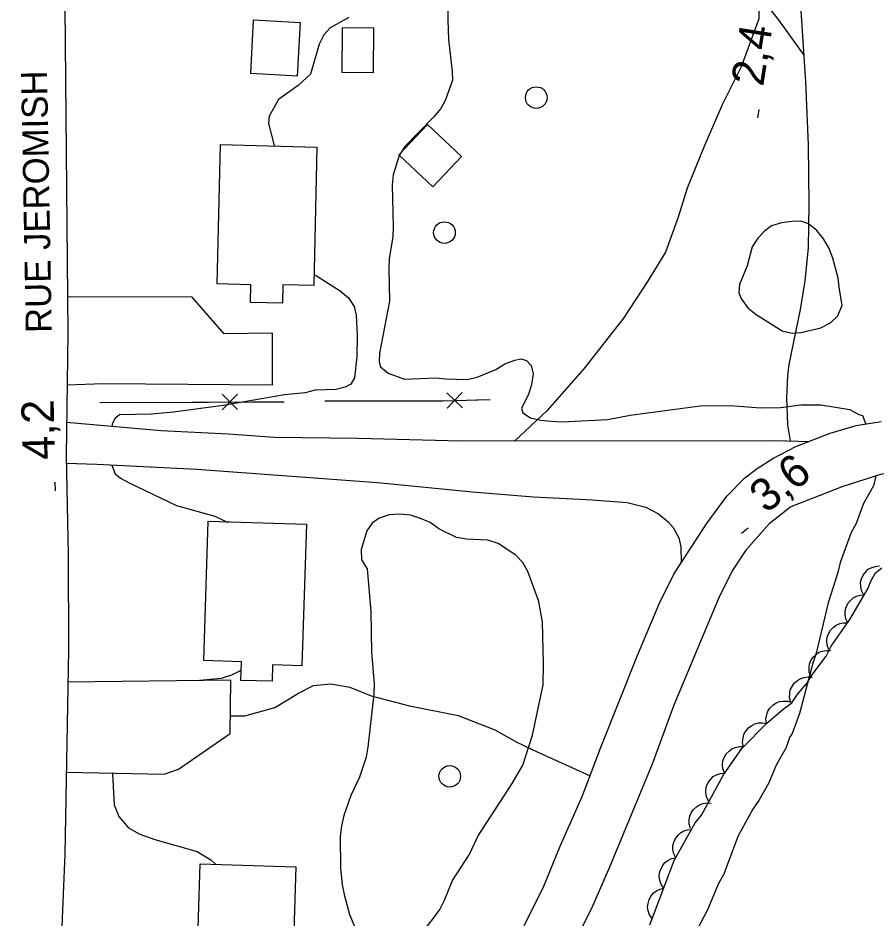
# Model space of a CAD drawing. Extents: x 282461 to 284471, y 5554090 to 5557646.
# Drawn here: x 283146.3 to 283225.6, y 5554850.5 to 5554933.8 of the extents above; entities that cross this region are included whole.
import ezdxf

# ---------------------------------------------------------------- set-up
doc = ezdxf.new("R2010")
doc.units = 0
for name, color, linetype in [('Niveau 15', 7, 'Continuous'), ('Niveau 19', 7, 'Continuous'), ('Niveau 2', 7, 'Continuous'), ('Niveau 21', 7, 'Continuous'), ('Niveau 22', 7, 'Continuous'), ('Niveau 3', 7, 'Continuous'), ('Niveau 31', 7, 'Continuous'), ('Niveau 36', 7, 'Continuous'), ('Niveau 37', 7, 'Continuous'), ('Niveau 44', 7, 'Continuous')]:
    doc.layers.add(name, color=color, linetype=linetype)

msp = doc.modelspace()

# ---------------------------------------------------------------- linework, layer by layer
at = {"layer": 'Niveau 19'}
for points in [[(283150.81, 5554899.91), (283154.12, 5554900.01), (283169.76, 5554899.91), (283169.76, 5554904.66), (283165.3, 5554904.62), (283162.36, 5554908.01), (283150.83, 5554908.02)], [(283150.76, 5554896.45), (283159.48, 5554895.68), (283165.68, 5554895.37), (283169.97, 5554895.05), (283177.68, 5554894.98), (283187.19, 5554894.71), (283216.24, 5554894.76), (283219.32, 5554894.67)], [(283150.73, 5554892.66), (283153.56, 5554892.58), (283162.77, 5554892.1), (283179.46, 5554890.87), (283188.23, 5554890.02), (283193.86, 5554889.56), (283199.32, 5554889.28), (283202.51, 5554889.03), (283204.26, 5554888.59), (283205.42, 5554887.98), (283206.3, 5554887.23), (283206.77, 5554886.71), (283207.31, 5554885.75), (283207.49, 5554884.94), (283207.51, 5554883.48)], [(283150.71, 5554864.1), (283159.76, 5554863.92), (283161.09, 5554864.39), (283165.86, 5554867.68), (283165.91, 5554872.6), (283150.88, 5554872.43)]]:
    msp.add_lwpolyline(points, dxfattribs=at)
at = {"layer": 'Niveau 2'}
for points in [[(283186, 5554935.57), (283185.96, 5554933.6), (283186.04, 5554931.8), (283186.37, 5554928.85), (283186.38, 5554928.04), (283185.76, 5554926.23), (283185.31, 5554925.42), (283184.68, 5554924.66), (283181.99, 5554921.91)], [(283176.82, 5554933.83), (283175.09, 5554932.89), (283174.52, 5554932.25), (283174.07, 5554931.38), (283173.29, 5554928.59), (283172.15, 5554927.54), (283170.31, 5554926.25), (283169.46, 5554924.73), (283169.41, 5554924.04), (283169.94, 5554922.01)], [(283181.99, 5554921.91), (283181.47, 5554921.1), (283180.92, 5554919.29), (283180.81, 5554918.37), (283180.92, 5554914.48), (283180.87, 5554913.56), (283180.55, 5554911.58), (283180.5, 5554910.6), (283180.59, 5554907.64), (283179.66, 5554902.82), (283179.62, 5554902.01), (283179.74, 5554901.55), (283180.44, 5554900.98), (283181.96, 5554900.41), (283184.85, 5554900.55), (283185.78, 5554900.44), (283187.76, 5554900.4), (283188.68, 5554900.59), (283190.41, 5554901.3), (283191.22, 5554901.83), (283192.14, 5554902.18), (283192.72, 5554902.3), (283193.24, 5554902.13), (283193.66, 5554901.67), (283193.84, 5554900.92), (283193.68, 5554899.94), (283193.4, 5554899.01), (283192.78, 5554897.73), (283192.9, 5554897.32), (283193.6, 5554896.86), (283194.53, 5554896.64), (283195.52, 5554896.53), (283196.5, 5554896.48), (283200.73, 5554896.7), (283202.79, 5554897.09), (283209.28, 5554897.96), (283212.06, 5554897.98), (283214.85, 5554897.78), (283216.7, 5554897.79), (283218.56, 5554898.04), (283220.41, 5554898.06), (283223.09, 5554897.62), (283223.91, 5554897.16), (283224.25, 5554897.05), (283224.56, 5554896.27)], [(283222.12, 5554908.72), (283222, 5554909.76), (283221.51, 5554911.61), (283221.15, 5554912.54), (283220.67, 5554913.4), (283220.03, 5554914.15), (283219.26, 5554914.78), (283218.56, 5554915.01), (283217.75, 5554915), (283216.77, 5554914.88), (283215.84, 5554914.58), (283215.21, 5554914.11), (283214.58, 5554913.46), (283214.06, 5554912.65), (283213.62, 5554910.9), (283212.89, 5554909.16), (283212.84, 5554908.4), (283213.08, 5554907.82), (283213.67, 5554907.02), (283214.43, 5554906.39), (283216.83, 5554904.9), (283217.76, 5554904.68), (283218.57, 5554904.74), (283220.42, 5554905.16), (283221.29, 5554905.64), (283221.98, 5554906.28), (283222.37, 5554907.27), (283222.12, 5554908.72)], [(283173.75, 5554910.04), (283176.03, 5554908.58), (283176.79, 5554907.95), (283177.32, 5554907.14), (283177.5, 5554906.33), (283177.58, 5554904.42), (283177.55, 5554902.51), (283177.34, 5554900.54), (283177, 5554899.96), (283176.48, 5554899.67), (283175.61, 5554899.48), (283173.7, 5554899.41), (283172.78, 5554899.17), (283170.87, 5554898.98), (283165.2, 5554898), (283160.63, 5554897.38)], [(283160.63, 5554897.38), (283158.61, 5554897.19), (283155.65, 5554897.11), (283155.25, 5554896.81), (283154.97, 5554896.29), (283154.95, 5554896.12)], [(283154.94, 5554892.48), (283155.25, 5554891.66), (283155.72, 5554891.26), (283156.6, 5554890.8), (283160.91, 5554888.76), (283164.46, 5554887.75), (283165.69, 5554887.18)], [(283225.48, 5554891.5), (283225.26, 5554890.57), (283224.35, 5554888.94), (283223.68, 5554887.08), (283223.22, 5554886.26), (283222.21, 5554883.47), (283221.99, 5554882.54), (283221.1, 5554879.75), (283219.99, 5554875.1), (283219.66, 5554874.17), (283218.43, 5554869.53), (283217.76, 5554867.67), (283217.53, 5554867.32), (283217.2, 5554866.39), (283216.29, 5554864.75), (283215.61, 5554863.13), (283214.7, 5554861.5), (283214.13, 5554860.68), (283212.77, 5554858.23), (283211.42, 5554854.63), (283210.97, 5554853.81), (283209.95, 5554851.37), (283207.8, 5554847.3)], [(283183.44, 5554849.08), (283184.64, 5554850.6), (283185.21, 5554851.42), (283185.67, 5554852.29), (283186.4, 5554854.09), (283187.94, 5554856.48), (283188.78, 5554858.23), (283191.92, 5554863.06), (283192.88, 5554864.75), (283193.78, 5554867.54), (283194.76, 5554872.19), (283194.8, 5554874.16), (283194.7, 5554877.98), (283194.38, 5554879.89), (283193.36, 5554882.66), (283192.89, 5554883.47), (283192.24, 5554884.16), (283190.61, 5554885.25), (283189.67, 5554885.53), (283187.7, 5554885.63), (283186.77, 5554885.79), (283185.14, 5554886.59), (283184.32, 5554887.16), (283183.44, 5554887.56), (283182.51, 5554887.84), (283181.53, 5554887.95), (283180.54, 5554887.88), (283179.62, 5554887.58), (283178.98, 5554887.11), (283178.47, 5554886.41), (283177.97, 5554884.67), (283177.98, 5554883.74), (283178.51, 5554882.88)], [(283178.51, 5554882.88), (283178.85, 5554878.94), (283178.9, 5554875.18), (283179.16, 5554872.28), (283179.12, 5554871.3), (283178.59, 5554866.42), (283178.43, 5554865.5), (283177.82, 5554863.64), (283177.02, 5554861.95), (283176.35, 5554860.09), (283176.13, 5554859.16), (283176.03, 5554858.17), (283176.06, 5554855.28), (283176.2, 5554853.71), (283176.38, 5554852.79), (283176.87, 5554850.94), (283177.64, 5554849.15)], [(283166.85, 5554873.5), (283165.97, 5554873.06), (283165.04, 5554872.76), (283163.04, 5554872.57)], [(283155.01, 5554864.01), (283155.01, 5554863.93), (283155.16, 5554861.09), (283155.58, 5554860), (283156.46, 5554858.96), (283157.51, 5554858.39), (283158.91, 5554857.88), (283162.8, 5554856.76), (283164.08, 5554856.02), (283164.52, 5554855.6)]]:
    msp.add_lwpolyline(points, dxfattribs=at)
at = {"layer": 'Niveau 21'}
for points in [[(283150.5, 5554944.9), (283150.87, 5554904.67), (283150.72, 5554893.32), (283150.89, 5554884.23), (283150.94, 5554875.39), (283150.59, 5554856.52), (283150.09, 5554844.69), (283149.99, 5554838.96), (283149.57, 5554834.94), (283148.73, 5554831.87), (283147.21, 5554828.07), (283145.57, 5554824.59)], [(283193.02, 5554849.93), (283194.77, 5554853.42), (283196.35, 5554857.26), (283198.38, 5554861.85), (283200.06, 5554866.32), (283203.44, 5554874.81), (283205.47, 5554879.67), (283206.82, 5554882.41), (283209.84, 5554887.05), (283211.72, 5554889.61), (283213.39, 5554891.29), (283214.54, 5554892.16), (283215.97, 5554893.08), (283218.11, 5554894.19), (283221.28, 5554895.44), (283223.66, 5554896.14), (283225.97, 5554896.5)], [(283289.42, 5554896.28), (283275.18, 5554894.5), (283271.87, 5554894.47), (283267.87, 5554894.26), (283258.82, 5554893.54), (283252.49, 5554893.15), (283241.46, 5554892.71), (283236.47, 5554892.62), (283230.2, 5554892.29), (283225.92, 5554891.61), (283222.45, 5554890.49), (283217.65, 5554888.62), (283215.64, 5554887.05), (283213.47, 5554884.61), (283212.21, 5554882.7), (283210.97, 5554880.15), (283206.85, 5554870.3), (283204.83, 5554864.86), (283200.89, 5554855.33), (283199.31, 5554851.72), (283197.05, 5554847.13)]]:
    msp.add_lwpolyline(points, dxfattribs=at)
at = {"layer": 'Niveau 22'}
for points in [[(283195.66, 5554972.41), (283200.29, 5554967.98), (283202.11, 5554965.96), (283205.64, 5554961.75), (283206.88, 5554960.02), (283208.42, 5554957.48), (283210.2, 5554954.32), (283214.56, 5554948.63), (283215.68, 5554946.73), (283216.75, 5554944.35), (283217.85, 5554940.36), (283218.48, 5554935.89), (283218.99, 5554927.89), (283219.23, 5554922.08), (283219.3, 5554916.61), (283219.23, 5554912.54), (283218.92, 5554909.52), (283218.49, 5554906.85), (283217.44, 5554901.76), (283217.34, 5554900.74), (283217.24, 5554898.73), (283217.33, 5554896.21), (283217.57, 5554894.72)], [(283184.19, 5554952.85), (283186.28, 5554951.71), (283192.1, 5554949.17), (283193.61, 5554948.48), (283195.13, 5554947.67), (283200.51, 5554944.12), (283202.85, 5554942.4), (283204.2, 5554941.61), (283211.13, 5554938.97), (283213.18, 5554937.45), (283215.24, 5554935.2), (283216.48, 5554933.64), (283218.83, 5554930.36)], [(283214.65, 5554935.84), (283214.68, 5554933.7), (283213.05, 5554929.27), (283211.29, 5554925.76), (283209.6, 5554921.86), (283208.08, 5554918.07), (283207.24, 5554915.4), (283206.06, 5554912.14), (283204.41, 5554909.45), (283202.18, 5554906.07), (283198.53, 5554901.38), (283195.1, 5554897.48), (283192.11, 5554894.7)], [(283165.88, 5554869.32), (283167.23, 5554869.31), (283170, 5554870.07), (283172.18, 5554871.41), (283173.56, 5554872.1), (283175.17, 5554872.28), (283176.91, 5554871.97), (283178.88, 5554871.15), (283182.43, 5554870.23), (283186.91, 5554869.34), (283190.29, 5554868.01), (283192.34, 5554866.88), (283194.2, 5554865.98), (283199.11, 5554863.78)]]:
    msp.add_lwpolyline(points, dxfattribs=at)
at = {"layer": 'Niveau 3'}
for p, q in [((283214.6, 5554924.56), (283214.72, 5554925.35)), ((283149.72, 5554890.11), (283149.7, 5554890.91)), ((283213.08, 5554886.19), (283213.71, 5554886.68))]:
    msp.add_line(p, q, dxfattribs=at)
at = {"layer": 'Niveau 31'}
for points in [[(283172.34, 5554933.39), (283172.06, 5554928.43), (283167.76, 5554928.67), (283168.03, 5554933.63), (283172.34, 5554933.39)], [(283176.2, 5554932.89), (283176.16, 5554928.78), (283179.09, 5554928.75), (283179.12, 5554932.86), (283176.2, 5554932.89)], [(283184.1, 5554923.96), (283181.44, 5554921.16), (283184.57, 5554918.18), (283187.24, 5554920.98), (283184.1, 5554923.96)], [(283173.88, 5554921.87), (283173.59, 5554909.07), (283170.74, 5554909.13), (283170.7, 5554907.43), (283167.74, 5554907.5), (283167.78, 5554909.14), (283164.65, 5554909.22), (283164.96, 5554922.09), (283173.88, 5554921.87)], [(283163.44, 5554874.41), (283163.84, 5554887.31), (283172.9, 5554887.02), (283172.49, 5554873.94), (283169.78, 5554874.03), (283169.74, 5554872.5), (283166.84, 5554872.59), (283166.9, 5554874.31), (283163.44, 5554874.41)], [(283171.92, 5554855.37), (283171.52, 5554842.41), (283168.89, 5554842.49), (283168.84, 5554840.91), (283165.96, 5554841), (283166.01, 5554842.68), (283162.7, 5554842.78), (283163.09, 5554855.64), (283171.92, 5554855.37)]]:
    msp.add_lwpolyline(points, dxfattribs=at)
at = {"layer": 'Niveau 36'}
for centre in [(283194.132, 5554926.435), (283185.65, 5554913.962), (283186.138, 5554863.722)]:
    msp.add_circle(centre, 1, dxfattribs=at)
at = {"layer": 'Niveau 37'}
for p, q in [((283166.54, 5554897.61), (283165.12, 5554899.02)), ((283165.13, 5554897.6), (283166.53, 5554899.03)), ((283187.33, 5554897.77), (283185.87, 5554899.15)), ((283185.91, 5554897.73), (283187.29, 5554899.18))]:
    msp.add_line(p, q, dxfattribs=at)
for points in [[(283153.83, 5554898.25), (283170.85, 5554898.34)], [(283153.83, 5554898.25), (283163.83, 5554898.3)], [(283167.83, 5554898.32), (283170.85, 5554898.34)], [(283174.6, 5554898.41), (283185.49, 5554898.43), (283189.88, 5554898.54)], [(283174.6, 5554898.41), (283184.6, 5554898.43)], [(283188.6, 5554898.51), (283189.88, 5554898.54)]]:
    msp.add_lwpolyline(points, dxfattribs=at)
at = {"layer": 'Niveau 44'}
for points in [[(283224.36, 5554880.52), (283224.17, 5554880.9), (283224.1, 5554881.3), (283224.08, 5554881.63), (283224.17, 5554881.97), (283224.32, 5554882.31), (283224.56, 5554882.61), (283224.79, 5554882.85), (283225.11, 5554883.01), (283225.46, 5554883.12), (283225.82, 5554883.16)], [(283225.01, 5554881.7), (283225.46, 5554882.51), (283226.03, 5554882.98)], [(283204.63, 5554850.01), (283206.88, 5554855.94), (283208.81, 5554859.43), (283209.38, 5554860.13), (283211.42, 5554863.86), (283213.13, 5554866.3), (283215.42, 5554868.64), (283216.92, 5554869.93), (283217.72, 5554870.51), (283218.29, 5554871.33), (283219.09, 5554872.26), (283219.66, 5554873.19), (283220.91, 5554874.83), (283221.37, 5554875.76), (283223.08, 5554878.2), (283224.78, 5554881.11), (283225.01, 5554881.7)], [(283222.9, 5554877.89), (283222.72, 5554878.27), (283222.66, 5554878.67), (283222.65, 5554879.01), (283222.74, 5554879.35), (283222.9, 5554879.68), (283223.15, 5554879.98), (283223.39, 5554880.2), (283223.7, 5554880.36), (283224.06, 5554880.47), (283224.42, 5554880.49)], [(283221.15, 5554875.44), (283221, 5554875.83), (283220.97, 5554876.24), (283220.99, 5554876.57), (283221.11, 5554876.9), (283221.3, 5554877.22), (283221.57, 5554877.5), (283221.82, 5554877.7), (283222.15, 5554877.83), (283222.51, 5554877.91), (283222.88, 5554877.91)], [(283219.48, 5554872.95), (283219.34, 5554873.35), (283219.33, 5554873.75), (283219.36, 5554874.08), (283219.5, 5554874.41), (283219.7, 5554874.72), (283219.98, 5554874.99), (283220.24, 5554875.18), (283220.57, 5554875.3), (283220.94, 5554875.36), (283221.3, 5554875.34)], [(283217.64, 5554870.57), (283217.53, 5554870.98), (283217.54, 5554871.38), (283217.59, 5554871.71), (283217.75, 5554872.03), (283217.96, 5554872.33), (283218.26, 5554872.58), (283218.53, 5554872.76), (283218.87, 5554872.86), (283219.24, 5554872.9), (283219.6, 5554872.86)], [(283215.38, 5554868.61), (283215.33, 5554869.03), (283215.41, 5554869.43), (283215.51, 5554869.74), (283215.71, 5554870.03), (283215.97, 5554870.3), (283216.3, 5554870.5), (283216.6, 5554870.64), (283216.95, 5554870.68), (283217.32, 5554870.67), (283217.67, 5554870.57)], [(283213.28, 5554866.45), (283213.19, 5554866.86), (283213.23, 5554867.27), (283213.31, 5554867.59), (283213.48, 5554867.9), (283213.72, 5554868.19), (283214.03, 5554868.41), (283214.31, 5554868.58), (283214.66, 5554868.65), (283215.03, 5554868.67), (283215.39, 5554868.61)], [(283211.52, 5554864.01), (283211.37, 5554864.4), (283211.34, 5554864.81), (283211.37, 5554865.14), (283211.49, 5554865.47), (283211.67, 5554865.79), (283211.94, 5554866.06), (283212.2, 5554866.27), (283212.53, 5554866.4), (283212.89, 5554866.48), (283213.25, 5554866.47)], [(283210.06, 5554861.37), (283209.87, 5554861.75), (283209.79, 5554862.15), (283209.78, 5554862.48), (283209.86, 5554862.82), (283210.01, 5554863.16), (283210.25, 5554863.46), (283210.48, 5554863.7), (283210.79, 5554863.86), (283211.15, 5554863.98), (283211.51, 5554864.02)], [(283208.37, 5554858.89), (283208.25, 5554859.29), (283208.25, 5554859.7), (283208.3, 5554860.03), (283208.44, 5554860.35), (283208.65, 5554860.66), (283208.94, 5554860.91), (283209.21, 5554861.1), (283209.55, 5554861.21), (283209.91, 5554861.26), (283210.27, 5554861.23)], [(283207.02, 5554856.19), (283206.83, 5554856.56), (283206.75, 5554856.96), (283206.74, 5554857.29), (283206.83, 5554857.64), (283206.98, 5554857.98), (283207.22, 5554858.28), (283207.45, 5554858.51), (283207.76, 5554858.67), (283208.11, 5554858.79), (283208.47, 5554858.82)], [(283205.91, 5554853.39), (283205.67, 5554853.73), (283205.54, 5554854.12), (283205.48, 5554854.44), (283205.52, 5554854.79), (283205.62, 5554855.15), (283205.81, 5554855.48), (283206.01, 5554855.75), (283206.29, 5554855.95), (283206.63, 5554856.12), (283206.98, 5554856.2)], [(283204.84, 5554850.57), (283204.6, 5554850.91), (283204.47, 5554851.3), (283204.41, 5554851.63), (283204.45, 5554851.98), (283204.55, 5554852.33), (283204.74, 5554852.67), (283204.94, 5554852.93), (283205.23, 5554853.14), (283205.56, 5554853.3), (283205.91, 5554853.39)]]:
    msp.add_lwpolyline(points, dxfattribs=at)

# ---------------------------------------------------------------- texts
at = {"layer": 'Niveau 15'}
msp.add_text('RUE JEROMISH', height=2.4, rotation=91.03925, dxfattribs=at).set_placement((283149.39, 5554904.71))
at = {"layer": 'Niveau 3'}
for s, height, rotation, p in [('2,4  ', 3, 81.09575, (283215.08, 5554927.4)), ('4,2  ', 2.9999, 91.36083, (283149.69, 5554892.99)), ('3,6  ', 3, 38.47822, (283215.36, 5554887.95))]:
    msp.add_text(s, height=height, rotation=rotation, dxfattribs=at).set_placement(p)

doc.saveas('drawing.dxf')
